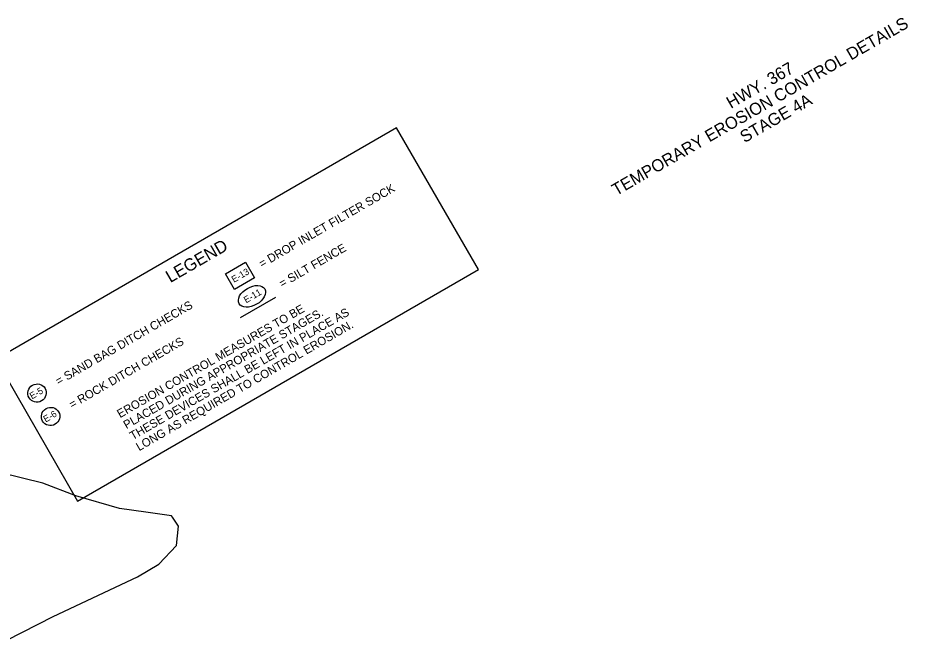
# Model space of a CAD drawing. Extents: x 1293866 to 1295382, y 223015 to 224618.
# Drawn here: x 1294723 to 1295382, y 223304 to 223764 of the extents above; entities that cross this region are included whole.
import ezdxf

# ---------------------------------------------------------------- set-up
doc = ezdxf.new("R2010")
doc.units = 0
for name, color, linetype in [('1', 7, 'Continuous'), ('60', 7, 'Continuous'), ('Level 1', 7, 'Continuous'), ('Level 44', 7, 'Continuous'), ('S_TREE', 7, 'Continuous')]:
    doc.layers.add(name, color=color, linetype=linetype)

msp = doc.modelspace()

# ---------------------------------------------------------------- linework, layer by layer
at = {"layer": '1'}
for p, q in [((1295002.97, 223683.01), (1294706.22, 223511.68)), ((1295063.5, 223578.18), (1295002.97, 223683.01))]:
    msp.add_line(p, q, dxfattribs=at)
msp.add_lwpolyline([(1294706.22, 223511.68), (1294766.75, 223406.85), (1295063.5, 223578.18)], dxfattribs=at)
at = {"layer": 'Level 1'}
msp.add_lwpolyline([(1294876.19, 223575.04), (1294891.01, 223583.6), (1294897.72, 223571.98), (1294882.9, 223563.42)], close=True, dxfattribs=at)
for centre, major_axis, ratio in [((1294895.89, 223558.41), (9.49, 5.48), 0.622952), ((1294736.84, 223486.84), (-5.96, -3.44), 0.97521), ((1294746.84, 223469.52), (-5.96, -3.44), 0.97521)]:
    msp.add_ellipse(centre, major_axis=major_axis, ratio=ratio, dxfattribs=at)
at = {"layer": 'Level 44'}
msp.add_lwpolyline([(1294887.51, 223542.8), (1294913.6, 223557.87)], dxfattribs=at)
at = {"layer": 'S_TREE'}
msp.add_lwpolyline([(1294714.57, 223303.99), (1294748.77, 223321.6), (1294811.07, 223350.92), (1294826.9, 223360.15), (1294840.15, 223374.15), (1294841.4, 223388.32), (1294837.11, 223394.97), (1294836.43, 223396.02), (1294817.43, 223398.61), (1294797.85, 223401.32), (1294765.55, 223410.69), (1294741.11, 223420.17), (1294709.95, 223427.78)], dxfattribs=at)
msp.add_lwpolyline([(1294714.57, 223303.99), (1294748.77, 223321.6), (1294811.07, 223350.92), (1294826.9, 223360.15), (1294840.15, 223374.15), (1294841.4, 223388.32), (1294837.11, 223394.97), (1294836.43, 223396.02), (1294817.43, 223398.61), (1294797.85, 223401.32), (1294765.55, 223410.69), (1294741.11, 223420.17), (1294709.95, 223427.78)], dxfattribs=at)

# ---------------------------------------------------------------- texts
at = {"layer": '60'}
for s, p in [('TEMPORARY EROSION CONTROL DETAILS', (1295165.49, 223632.47)), ('HWY. 367', (1295250.31, 223697.03)), ('STAGE 4A', (1295260.4, 223671.68))]:
    msp.add_text(s, height=9, rotation=30, dxfattribs=at).set_placement(p)
at = {"layer": 'Level 1'}
for s, height, p in [('= DROP INLET FILTER SOCK', 6.25, (1294903.25, 223579.31)), ('= SILT FENCE', 6.25, (1294918.21, 223564.63)), ('E-13', 4.876, (1294882.52, 223568.38)), ('E-11 ', 4.876, (1294891.55, 223553.14)), ('= SAND BAG DITCH CHECKS', 6.25, (1294752.72, 223492.4)), ('EROSION CONTROL MEASURES TO BE', 6.25, (1294798.26, 223468.19)), ('PLACED DURING APPROPRIATE STAGES. ', 6.25, (1294802.97, 223460.04)), ('THESE DEVICES SHALL BE LEFT IN PLACE AS ', 6.25, (1294807.68, 223451.9)), ('LONG AS REQUIRED TO CONTROL EROSION.', 6.25, (1294812.38, 223443.75)), ('= ROCK DITCH CHECKS', 6.25, (1294762.72, 223475.08)), ('E-5 ', 4.876, (1294733.07, 223482.1)), ('E-6 ', 4.876, (1294743.21, 223464.97))]:
    msp.add_text(s, height=height, rotation=30.00011, dxfattribs=at).set_placement(p)
at = {"layer": 'Level 44'}
msp.add_text('LEGEND', height=9.143, rotation=30.00011, dxfattribs=at).set_placement((1294835.43, 223568.15))

doc.saveas('drawing.dxf')
